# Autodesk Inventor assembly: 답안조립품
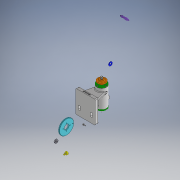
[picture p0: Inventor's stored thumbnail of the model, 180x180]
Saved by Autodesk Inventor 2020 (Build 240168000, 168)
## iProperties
Created: 2021-11
Part Number: 답안조립품
Document SubType Name: Assembly
Designer: user
Author: user
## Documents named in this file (18)
- C:\Users\user\Desktop\711112V1006 (1)\답안조립품.iam
- C:\Users\user\Desktop\711112V1006 (1)\나사.ipt
- C:\Users\user\Desktop\711112V1006 (1)\나사축.ipt
- C:\Users\user\Desktop\711112V1006 (1)\너트 M8.ipt
- C:\Users\user\Desktop\711112V1006 (1)\돌림판.ipt
- C:\Users\user\Desktop\711112V1006 (1)\멈춤나사 M3.ipt
- C:\Users\user\Desktop\711112V1006 (1)\본체.ipt
- C:\Users\user\Desktop\711112V1006 (1)\볼트 M3.ipt
- C:\Users\user\Desktop\711112V1006 (1)\부시.ipt
- C:\Users\user\Desktop\711112V1006 (1)\센터.ipt
- C:\Users\user\Desktop\711112V1006 (1)\센터홀더.ipt
- C:\Users\user\Desktop\711112V1006 (1)\슬리브.ipt
- C:\Users\user\Desktop\711112V1006 (1)\와셔.ipt
- C:\Users\user\Desktop\711112V1006 (1)\중공축.ipt
- C:\Users\user\Desktop\711112V1006 (1)\커버.ipt
- C:\Users\user\Desktop\711112V1006 (1)\키 4 x 4 x 10.ipt
- C:\Users\user\Desktop\711112V1006 (1)\플랜지.ipt
- C:\Users\user\Desktop\711112V1006 (1)\핸들.ipt
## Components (2 placed, 2 different names)
1. 플랜지:1
2. 핸들:1
